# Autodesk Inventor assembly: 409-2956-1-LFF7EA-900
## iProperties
Created: 2010-09
Part Number: 409-2956-1-LFF7EA-900
Document SubType Name: Assembly
Designer: S. Boerckel
Mass: 2.7134e+06 g
Surface Area: 791272 cm^2
Volume: 404258 cm^3
Density: 6.71204 g/cm^3
Description: GENERAL ARRANGEMENT
Material: ASSEMBLY
SMR: =<MATERIAL>
Author: S. Boerckel
Revision Number: 0
